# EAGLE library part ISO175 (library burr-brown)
Isolated Instrumentation Amplifier Precision
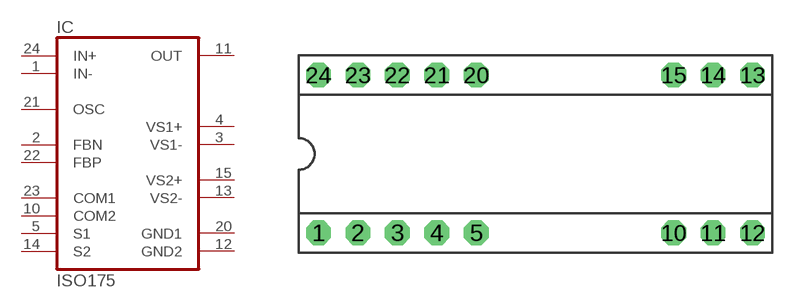
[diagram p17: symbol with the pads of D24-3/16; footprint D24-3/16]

Designator prefix IC

## ISO175P (OC_FARNELL: unknown; OC_NEWARK: unknown)  [D24-3/16]
1  IN-  in
2  FBN  pas
3  VS1-  pwr
4  VS1+  pwr
5  S1  pas
10  COM2  pas
11  OUT  out
12  GND2  pwr
13  VS2-  pwr
14  S2  pas
15  VS2+  pwr
20  GND1  pwr
21  OSC  in
22  FBP  pas
23  COM1  pas
24  IN+  in

## Footprint D24-3/16 (pad centres in mm)
Dual In Line 0.4 inch
drill 0.813 pad 1.6 octagon: 1 -13.97,-5.08; 2 -11.43,-5.08; 3 -8.89,-5.08; 4 -6.35,-5.08; 5 -3.81,-5.08; 10 8.89,-5.08; 11 11.43,-5.08; 12 13.97,-5.08; 13 13.97,5.08; 14 11.43,5.08; 15 8.89,5.08; 20 -3.81,5.08; 21 -6.35,5.08; 22 -8.89,5.08; 23 -11.43,5.08; 24 -13.97,5.08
